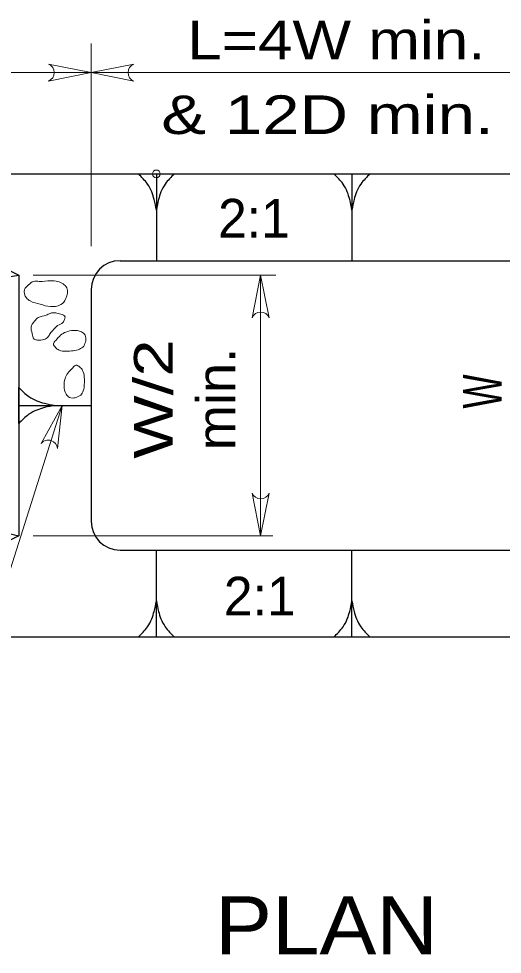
# Model space of a CAD drawing. Extents: x 1043.1 to 1101.1, y 672.4 to 716.4.
# Drawn here: x 1058.032 to 1060.033, y 702.156 to 706.032 of the extents above; entities that cross this region are included whole.
import ezdxf
from ezdxf.enums import TextEntityAlignment as Align

# ---------------------------------------------------------------- set-up
doc = ezdxf.new("R2010")
doc.units = 0
doc.header["$LTSCALE"] = 0.064
doc.header["$PDMODE"] = 32
doc.header["$PDSIZE"] = 0.032
doc.layers.add('1', color=7, linetype='Continuous', lineweight=13)

msp = doc.modelspace()

# ---------------------------------------------------------------- linework, layer by layer
at = {"layer": '1'}
for p, q in [((1058.33175, 705.92883), (1058.33175, 705.08933)), ((1058.33175, 705.80883), (1060.43058, 705.80883)), ((1058.09183, 704.96942), (1059.0955, 704.96942)), ((1058.09183, 703.89), (1059.0835, 703.89))]:
    msp.add_line(p, q, dxfattribs=at)
at = {"layer": '1', "lineweight": 25}
for p, q in [((1058.52658, 705.38908), (1058.6765, 705.38908)), ((1058.6015, 705.38908), (1058.6015, 705.02725)), ((1059.33625, 705.38908), (1059.48608, 705.38908)), ((1059.41108, 705.38908), (1059.41108, 705.02933)), ((1058.45158, 705.02933), (1060.31075, 705.02933)), ((1056.47258, 704.7295), (1058.03183, 704.96942)), ((1058.33175, 704.90942), (1058.33175, 703.95)), ((1058.03183, 704.35475), (1058.03183, 704.50458)), ((1058.03183, 704.42975), (1058.33175, 704.42975)), ((1056.47258, 704.24983), (1058.03183, 703.89)), ((1058.45158, 703.83), (1060.31075, 703.83)), ((1058.6015, 703.47033), (1058.6015, 703.83)), ((1059.41108, 703.47033), (1059.41108, 703.83175)), ((1058.6765, 703.47033), (1058.52658, 703.47033)), ((1059.48608, 703.47033), (1059.33625, 703.47033)), ((1059.48608, 703.47033), (1059.33625, 703.47033))]:
    msp.add_line(p, q, dxfattribs=at)
at = {"layer": '1'}
for points in [[(1056.47258, 705.92883), (1056.47258, 705.80883), (1058.33175, 705.80883)], [(1058.15517, 705.84417), (1058.33175, 705.80883), (1058.15517, 705.77358), (1058.15517, 705.77367)], [(1058.50825, 705.77358), (1058.33175, 705.80883), (1058.50825, 705.84417), (1058.50825, 705.84408)], [(1058.998, 704.79283), (1059.03333, 704.96942), (1059.06867, 704.79283), (1059.06858, 704.79283)], [(1059.03333, 704.96942), (1059.03333, 704.30983), (1059.03333, 703.89)], [(1058.21175, 704.42975), (1057.72983, 702.91025), (1057.24858, 702.91025)], [(1058.12475, 704.27217), (1058.21175, 704.42975), (1058.19208, 704.25083), (1058.192, 704.25083)], [(1059.06867, 704.06658), (1059.03333, 703.89), (1058.998, 704.06658), (1058.99817, 704.06658)]]:
    msp.add_lwpolyline(points, dxfattribs=at)
at = {"layer": '1', "lineweight": 25}
for points in [[(1057.91192, 705.38908), (1059.41108, 705.38908), (1060.91042, 705.38908)], [(1057.79192, 705.08933), (1058.03183, 704.96942), (1058.03183, 703.89), (1057.79192, 703.77008)], [(1060.91042, 703.47033), (1059.41108, 703.47033), (1057.91192, 703.47033)]]:
    msp.add_lwpolyline(points, dxfattribs=at)
at = {"layer": '1'}
for centre, start, end in [((1058.14084, 705.80894), 292.08789, 67.91402), ((1058.5226, 705.8088), 112.08789, 247.91402), ((1059.0333, 704.77851), 22.08789, 157.91402), ((1058.15402, 704.24784), 4.49122, 140.31734), ((1059.03342, 704.08089), 202.08789, 337.91402)]:
    msp.add_arc(centre, 0.03811, start, end, dxfattribs=at)
at = {"layer": '1', "lineweight": 25}
for centre, start_param, end_param in [((1058.45163, 704.90941), 4.712389, 6.2831853), ((1058.45163, 703.94999), 6.2831853, 7.8539816)]:
    msp.add_ellipse(centre, major_axis=(-0.11994, 0), ratio=0.999895, start_param=start_param, end_param=end_param, dxfattribs=at)
for points in [[(1058.6015, 705.23925), (1058.5925, 705.28283), (1058.5825, 705.31408), (1058.56483, 705.347), (1058.52658, 705.38908)], [(1058.6765, 705.38908), (1058.63833, 705.347), (1058.62058, 705.31408), (1058.6105, 705.28283), (1058.6015, 705.23925)], [(1059.41108, 705.23925), (1059.40208, 705.28283), (1059.392, 705.31408), (1059.37442, 705.347), (1059.33625, 705.38908)], [(1059.48608, 705.38908), (1059.44792, 705.347), (1059.43025, 705.31408), (1059.42008, 705.28283), (1059.41108, 705.23925)], [(1058.03183, 704.50458), (1058.07392, 704.4665), (1058.10692, 704.44883), (1058.13825, 704.43875), (1058.18183, 704.42975)], [(1058.18183, 704.42975), (1058.13825, 704.42075), (1058.10692, 704.41058), (1058.07392, 704.39292), (1058.03183, 704.35475)], [(1058.52658, 703.47033), (1058.56483, 703.51233), (1058.5825, 703.54533), (1058.5925, 703.57658), (1058.6015, 703.62025)], [(1058.6015, 703.62025), (1058.6105, 703.57658), (1058.62058, 703.54533), (1058.63833, 703.51233), (1058.6765, 703.47033)], [(1059.33625, 703.47033), (1059.37442, 703.51233), (1059.392, 703.54533), (1059.40208, 703.57658), (1059.41108, 703.62025)], [(1059.33625, 703.47033), (1059.37442, 703.51233), (1059.392, 703.54533), (1059.40208, 703.57658), (1059.41108, 703.62025)], [(1059.41108, 703.62025), (1059.42008, 703.57658), (1059.43025, 703.54533), (1059.44792, 703.51233), (1059.48608, 703.47033)], [(1059.41108, 703.62025), (1059.42008, 703.57658), (1059.43025, 703.54533), (1059.44792, 703.51233), (1059.48608, 703.47033)]]:
    msp.add_spline(points, degree=3, dxfattribs=at)
at = {"layer": '1'}
for points in [[(1058.184, 704.83958), (1058.20608, 704.84725), (1058.22742, 704.87283), (1058.23058, 704.91692), (1058.19383, 704.9435), (1058.16383, 704.94658), (1058.11658, 704.9435), (1058.09308, 704.9435), (1058.07283, 704.92983), (1058.056, 704.90958), (1058.06342, 704.87525), (1058.0795, 704.86258), (1058.12008, 704.849), (1058.16383, 704.83925), (1058.184, 704.83958)], [(1058.18492, 704.81325), (1058.20558, 704.80833), (1058.22342, 704.79642), (1058.221, 704.78608), (1058.21483, 704.77308), (1058.19275, 704.76025), (1058.17708, 704.74525), (1058.16175, 704.72725), (1058.15275, 704.71308), (1058.13642, 704.703), (1058.10992, 704.70042), (1058.09575, 704.70492), (1058.08725, 704.72758), (1058.08275, 704.754), (1058.09725, 704.779), (1058.11242, 704.794), (1058.14542, 704.8035), (1058.1615, 704.81133), (1058.18492, 704.81325)], [(1058.30075, 704.67475), (1058.2835, 704.66275), (1058.25783, 704.65642), (1058.22692, 704.65425), (1058.19925, 704.65883), (1058.184, 704.66975), (1058.17583, 704.68508), (1058.18492, 704.69875), (1058.20525, 704.72108), (1058.22733, 704.73392), (1058.25775, 704.7405), (1058.29133, 704.73458), (1058.30633, 704.72125), (1058.30958, 704.69783), (1058.30075, 704.67475)], [(1058.28833, 704.47233), (1058.29892, 704.49033), (1058.30325, 704.51642), (1058.303, 704.54742), (1058.29633, 704.57475), (1058.28425, 704.589), (1058.26825, 704.59608), (1058.25542, 704.58583), (1058.23458, 704.56383), (1058.22358, 704.54083), (1058.21942, 704.51), (1058.22792, 704.477), (1058.24242, 704.46308), (1058.266, 704.46175), (1058.28833, 704.47233)]]:
    msp.add_spline(points, degree=3, dxfattribs=at)
msp.add_point((1058.6015, 705.38908), dxfattribs=at)

# ---------------------------------------------------------------- texts
for s, width, p in [('L=4W min.', 1.2, (1058.72958, 705.86342)), ('& 12D min.', 1.3, (1058.62192, 705.55433))]:
    msp.add_text(s, height=0.16, dxfattribs=dict(at, width=width)).set_placement(p)
for p in [(1058.85683, 705.1255), (1058.88083, 703.56)]:
    msp.add_text('2:1', height=0.16, dxfattribs=at).set_placement(p)
for s, width, p in [('W/2', 1.3, (1058.66892, 704.45625)), ('min.', 1.05, (1058.92892, 704.45625))]:
    msp.add_text(s, height=0.16, rotation=90, dxfattribs=dict(at, width=width)).set_placement(p, align=Align.CENTER)
at = {"layer": '1', "width": 0.7}
msp.add_text('W', height=0.16, rotation=90, dxfattribs=at).set_placement((1060.03142, 704.417))
at = {"layer": '1', "width": 1.1}
msp.add_text('PLAN', height=0.24, dxfattribs=at).set_placement((1059.306, 702.15592), align=Align.CENTER)

doc.saveas('drawing.dxf')
